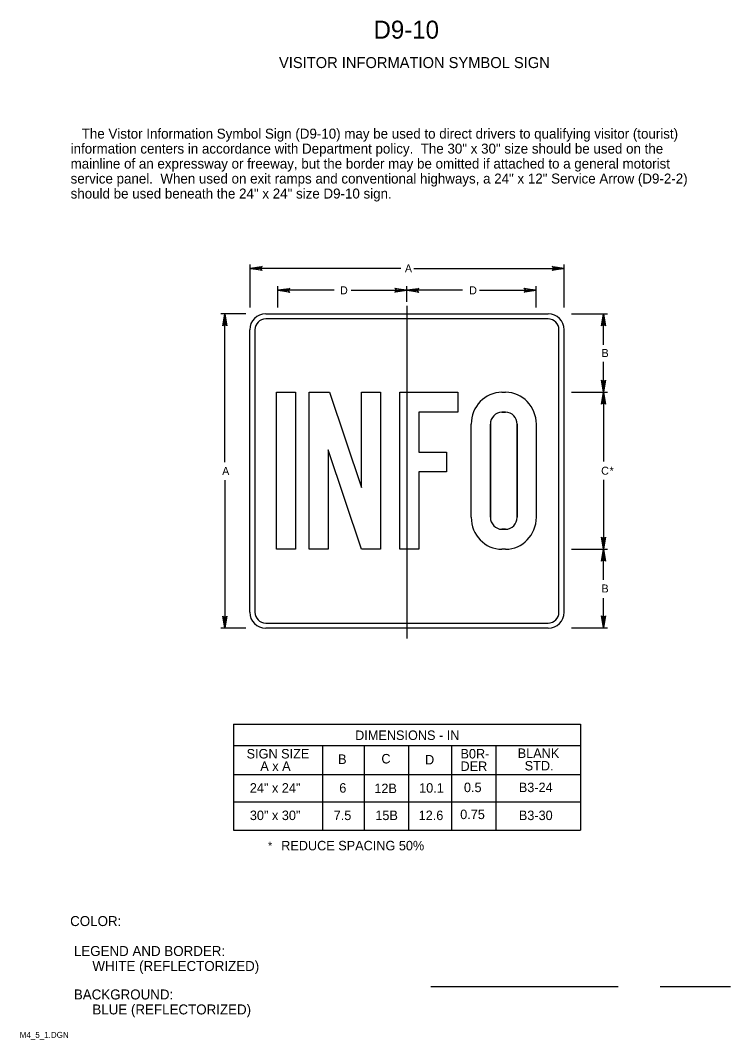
# Model space of a CAD drawing. Extents: x 0.013 to 0.191, y 0.004 to 0.259.
import ezdxf

# ---------------------------------------------------------------- set-up
doc = ezdxf.new("R2010")
doc.units = 0
doc.layers.add('1', color=7, linetype='Continuous')
doc.layers.add('3', color=7, linetype='Continuous')

# ---------------------------------------------------------------- blocks, each defined once
blk = doc.blocks.new('RARROW')
at = {"layer": '3'}
for p, q in [((-2.156, 0.285), (-2.2665, 0.384625)), ((-2.2665, 0.384625), (0, 0)), ((0, 0), (-2.2665, -0.379125)), ((-2.156, 0.285), (-2.075625, 0.12075)), ((0, 0), (-2.156, 0.285)), ((-2.14975, -0.2705), (0, 0)), ((-2.075625, 0.12075), (0, 0)), ((0, 0), (-2.074, -0.108)), ((-2.2665, -0.379125), (-2.14975, -0.2705)), ((-2.074, -0.108), (-2.14975, -0.2705))]:
    blk.add_line(p, q, dxfattribs=at)

msp = doc.modelspace()

# ---------------------------------------------------------------- linework, layer by layer
at = {"layer": '1'}
for p, q in [((0.11544, 0.01723), (0.16242, 0.01723)), ((0.17295, 0.01723), (0.19056, 0.01723))]:
    msp.add_line(p, q, dxfattribs=at)
at = {"layer": '3'}
for p, q in [((0.07023, 0.18733), (0.07023, 0.19809)), ((0.10798, 0.19709), (0.07023, 0.19709)), ((0.11123, 0.19709), (0.14886, 0.19709)), ((0.14886, 0.18733), (0.14886, 0.19809)), ((0.07713, 0.18733), (0.07713, 0.19259)), ((0.09122, 0.19159), (0.07713, 0.19159)), ((0.09549, 0.19159), (0.10948, 0.19159)), ((0.10948, 0.18872), (0.10948, 0.19259)), ((0.12343, 0.19159), (0.10948, 0.19159)), ((0.12769, 0.19159), (0.14183, 0.19159)), ((0.14183, 0.18733), (0.14183, 0.19259)), ((0.10948, 0.18772), (0.10948, 0.10443)), ((0.06915, 0.18572), (0.0629, 0.18572)), ((0.0639, 0.14859), (0.0639, 0.18572)), ((0.07411, 0.18572), (0.14486, 0.18572)), ((0.14486, 0.18442), (0.07411, 0.18442)), ((0.15073, 0.18572), (0.15973, 0.18572)), ((0.15873, 0.17794), (0.15873, 0.18572)), ((0.07011, 0.11097), (0.07011, 0.18172)), ((0.07141, 0.18172), (0.07141, 0.11097)), ((0.14886, 0.11097), (0.14886, 0.18172)), ((0.14886, 0.11097), (0.14886, 0.18172)), ((0.15873, 0.16606), (0.15873, 0.17372)), ((0.07678, 0.12675), (0.07678, 0.16606)), ((0.07678, 0.16606), (0.08159, 0.16606)), ((0.08159, 0.16606), (0.08159, 0.12675)), ((0.08496, 0.12675), (0.08496, 0.16606)), ((0.08496, 0.16606), (0.09013, 0.16606)), ((0.09013, 0.16606), (0.09807, 0.14223)), ((0.09807, 0.14223), (0.09807, 0.16606)), ((0.09807, 0.16606), (0.10289, 0.16606)), ((0.10289, 0.16606), (0.10289, 0.12675)), ((0.1077, 0.12675), (0.1077, 0.16606)), ((0.1077, 0.16606), (0.12221, 0.16606)), ((0.12221, 0.16606), (0.12221, 0.16106)), ((0.15073, 0.16606), (0.15973, 0.16606)), ((0.15873, 0.16606), (0.15873, 0.14869)), ((0.12221, 0.16106), (0.11251, 0.16106)), ((0.11251, 0.16106), (0.11251, 0.1511)), ((0.13328, 0.16106), (0.1342, 0.16106)), ((0.12558, 0.13475), (0.12558, 0.15806)), ((0.13039, 0.13475), (0.13039, 0.15806)), ((0.13709, 0.15806), (0.13709, 0.13475)), ((0.1419, 0.15806), (0.1419, 0.13475)), ((0.09807, 0.12675), (0.08978, 0.15163)), ((0.08978, 0.15163), (0.08978, 0.12675)), ((0.11251, 0.1511), (0.11937, 0.1511)), ((0.11937, 0.1511), (0.11937, 0.1461)), ((0.11937, 0.1461), (0.11251, 0.1461)), ((0.11251, 0.1461), (0.11251, 0.12675)), ((0.0639, 0.14406), (0.0639, 0.10697)), ((0.15873, 0.14412), (0.15873, 0.12675)), ((0.1342, 0.13175), (0.13328, 0.13175)), ((0.08159, 0.12675), (0.07678, 0.12675)), ((0.08978, 0.12675), (0.08496, 0.12675)), ((0.10289, 0.12675), (0.09807, 0.12675)), ((0.11251, 0.12675), (0.1077, 0.12675)), ((0.1342, 0.12675), (0.13328, 0.12675)), ((0.15073, 0.12675), (0.15973, 0.12675)), ((0.15873, 0.11912), (0.15873, 0.12675)), ((0.15873, 0.10709), (0.15873, 0.11447)), ((0.06915, 0.10697), (0.0629, 0.10697)), ((0.14486, 0.10697), (0.07411, 0.10697)), ((0.15073, 0.10709), (0.15973, 0.10709)), ((0.06602, 0.08298), (0.15294, 0.08298)), ((0.06606, 0.08298), (0.06606, 0.05641)), ((0.15294, 0.08298), (0.15294, 0.05641)), ((0.15294, 0.07754), (0.06606, 0.07754)), ((0.08831, 0.07754), (0.08831, 0.05641)), ((0.0988, 0.07754), (0.0988, 0.05641)), ((0.10992, 0.07754), (0.10992, 0.05641)), ((0.12069, 0.07754), (0.12069, 0.05641)), ((0.13175, 0.07754), (0.13175, 0.05641)), ((0.06606, 0.07031), (0.15294, 0.07031)), ((0.06606, 0.06351), (0.15294, 0.06351)), ((0.06606, 0.05641), (0.15294, 0.05641))]:
    msp.add_line(p, q, dxfattribs=at)
for points in [[(0.14486, 0.18442), (0.07411, 0.18442)], [(0.14486, 0.18442), (0.07411, 0.18442)], [(0.14486, 0.18442), (0.07411, 0.18442)], [(0.14486, 0.18442), (0.07411, 0.18442)], [(0.14486, 0.18442), (0.07411, 0.18442)], [(0.14486, 0.18442), (0.07411, 0.18442)], [(0.14486, 0.18442), (0.07411, 0.18442), (0.07411, 0.18442)], [(0.14486, 0.18442), (0.14486, 0.18442)], [(0.07141, 0.18172), (0.07141, 0.11097)], [(0.07141, 0.18172), (0.07141, 0.11097)], [(0.07141, 0.18172), (0.07141, 0.11097)], [(0.07141, 0.18172), (0.07141, 0.11097)], [(0.07141, 0.18172), (0.07141, 0.11097)], [(0.07141, 0.18172), (0.07141, 0.11097)], [(0.07141, 0.18172), (0.07141, 0.11097), (0.07141, 0.11097)], [(0.14756, 0.11097), (0.14756, 0.18172)], [(0.14756, 0.11097), (0.14756, 0.18172)], [(0.14756, 0.11097), (0.14756, 0.18172)], [(0.14756, 0.11097), (0.14756, 0.18172)], [(0.14756, 0.11097), (0.14756, 0.18172)], [(0.14756, 0.11097), (0.14756, 0.18172)], [(0.14756, 0.11097), (0.14756, 0.18172)], [(0.14756, 0.11097), (0.14756, 0.18172)], [(0.08159, 0.12675), (0.07678, 0.12675), (0.07678, 0.16606), (0.08159, 0.16606), (0.08159, 0.12675)], [(0.08978, 0.12675), (0.08496, 0.12675), (0.08496, 0.16606), (0.09013, 0.16606), (0.09807, 0.14223), (0.09807, 0.16606), (0.10289, 0.16606), (0.10289, 0.12675), (0.09807, 0.12675), (0.08978, 0.15163), (0.08978, 0.12675)], [(0.11251, 0.12675), (0.1077, 0.12675), (0.1077, 0.16606), (0.12221, 0.16606), (0.12221, 0.16106), (0.11251, 0.16106), (0.11251, 0.1511), (0.11937, 0.1511), (0.11937, 0.1461), (0.11251, 0.1461), (0.11251, 0.12675)], [(0.13328, 0.16606), (0.1342, 0.16606)], [(0.1342, 0.16106), (0.13328, 0.16106)], [(0.12558, 0.13475), (0.12558, 0.15806)], [(0.13039, 0.15806), (0.13039, 0.13475)], [(0.13709, 0.13475), (0.13709, 0.15806)], [(0.1419, 0.15806), (0.1419, 0.13475)], [(0.13328, 0.13175), (0.1342, 0.13175)], [(0.1342, 0.12675), (0.13328, 0.12675)], [(0.07411, 0.10827), (0.14486, 0.10827)], [(0.07411, 0.10827), (0.14486, 0.10827)], [(0.07411, 0.10827), (0.14486, 0.10827)], [(0.07411, 0.10827), (0.14486, 0.10827)], [(0.07411, 0.10827), (0.14486, 0.10827)], [(0.07411, 0.10827), (0.14486, 0.10827)], [(0.07411, 0.10827), (0.14486, 0.10827)], [(0.07411, 0.10827), (0.14486, 0.10827)]]:
    msp.add_lwpolyline(points, dxfattribs=at)
for centre, radius, start, end in [((0.07411, 0.18172), 0.004, 90, 180), ((0.07411, 0.18172), 0.0027, 90, 180), ((0.07411, 0.18172), 0.0027, 90, 180), ((0.07411, 0.18172), 0.0027, 90, 180), ((0.07411, 0.18172), 0.0027, 90, 180), ((0.07411, 0.18172), 0.0027, 90, 180), ((0.07411, 0.18172), 0.0027, 90, 180), ((0.07411, 0.18172), 0.0027, 90, 180), ((0.07411, 0.18172), 0.0027, 90, 180), ((0.14486, 0.18172), 0.004, 0, 90), ((0.14486, 0.18172), 0.0027, 360, 90), ((0.14486, 0.18172), 0.0027, 360, 90), ((0.14486, 0.18172), 0.0027, 360, 90), ((0.14486, 0.18172), 0.0027, 360, 90), ((0.14486, 0.18172), 0.0027, 360, 90), ((0.14486, 0.18172), 0.0027, 360, 90), ((0.14486, 0.18172), 0.0027, 360, 90), ((0.14486, 0.18172), 0.0027, 360, 90), ((0.07411, 0.11097), 0.004, 180, 270), ((0.07411, 0.11097), 0.0027, 180, 270), ((0.07411, 0.11097), 0.0027, 180, 270), ((0.07411, 0.11097), 0.0027, 180, 270), ((0.07411, 0.11097), 0.0027, 180, 270), ((0.07411, 0.11097), 0.0027, 180, 270), ((0.07411, 0.11097), 0.0027, 180, 270), ((0.07411, 0.11097), 0.0027, 180, 270), ((0.07411, 0.11097), 0.0027, 180, 270), ((0.14486, 0.11097), 0.004, 270, 0), ((0.14486, 0.11097), 0.0027, 270, 0), ((0.14486, 0.11097), 0.0027, 270, 0), ((0.14486, 0.11097), 0.0027, 270, 0), ((0.14486, 0.11097), 0.0027, 270, 0), ((0.14486, 0.11097), 0.0027, 270, 0), ((0.14486, 0.11097), 0.0027, 270, 0), ((0.14486, 0.11097), 0.0027, 270, 0), ((0.14486, 0.11097), 0.0027, 270, 0)]:
    msp.add_arc(centre, radius, start, end, dxfattribs=at)
for centre, major_axis, start_param, end_param in [((0.13328, 0.15806), (0, 0.008), 0, 1.570796), ((0.13328, 0.15806), (0, 0.008), 0, 1.570796), ((0.1342, 0.15806), (0, 0.008), 4.712389, 6.283185), ((0.1342, 0.15806), (0, 0.008), 4.712389, 6.283185), ((0.13328, 0.15806), (0, 0.003), 0, 1.570796), ((0.13328, 0.15806), (0, 0.003), 0, 1.570796), ((0.1342, 0.15806), (0, 0.003), 4.712389, 6.283185), ((0.1342, 0.15806), (0, 0.003), 4.712389, 6.283185), ((0.13328, 0.13475), (0, -0.008), 4.712389, 6.283185), ((0.13328, 0.13475), (0, -0.008), 4.712389, 6.283185), ((0.13328, 0.13475), (0, -0.003), 4.712389, 6.283185), ((0.13328, 0.13475), (0, -0.003), 4.712389, 6.283185), ((0.1342, 0.13475), (0, -0.008), 0, 1.570796), ((0.1342, 0.13475), (0, -0.003), 0, 1.570796), ((0.1342, 0.13475), (0, -0.008), 0, 1.570796), ((0.1342, 0.13475), (0, -0.003), 0, 1.570796)]:
    msp.add_ellipse(centre, major_axis=major_axis, ratio=0.962529, start_param=start_param, end_param=end_param, dxfattribs=at)

# ---------------------------------------------------------------- block references
at = {"layer": '3', "xscale": 0.0013236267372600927, "yscale": 0.001309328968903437}
for p, rotation in [((0.07023, 0.19709), 180), ((0.07713, 0.19159), 180), ((0.10948, 0.19159), 180), ((0.0639, 0.18572), 90), ((0.15873, 0.18572), 90), ((0.15873, 0.16606), -90), ((0.15873, 0.16606), 90), ((0.15873, 0.12675), -90), ((0.15873, 0.12675), 90), ((0.0639, 0.10697), -90), ((0.15873, 0.10709), -90)]:
    msp.add_blockref('RARROW', p, dxfattribs=dict(at, rotation=rotation))
for p in [(0.14886, 0.19709), (0.10948, 0.19159), (0.14183, 0.19159)]:
    msp.add_blockref('RARROW', p, dxfattribs=at)

# ---------------------------------------------------------------- texts
at = {"layer": '1'}
for s, height, p in [('D9-10', 0.0045, (0.10113, 0.25462)), ('VISITOR INFORMATION SYMBOL SIGN', 0.0027503, (0.07744, 0.24725)), ('   The Vistor Information Symbol Sign (D9-10) may be used to direct drivers to qualifying visitor (tourist)', 0.00249975, (0.02525, 0.22958)), ('information centers in accordance with Department policy.  The 30" x 30" size should be used on the', 0.0024998, (0.02525, 0.22583)), ('mainline of an expressway or freeway, but the border may be omitted if attached to a general motorist', 0.00249975, (0.02525, 0.22208)), ('service panel.  When used on exit ramps and conventional highways, a 24" x 12" Service Arrow (D9-2-2)', 0.00249975, (0.02525, 0.21833)), ('should be used beneath the 24" x 24" size D9-10 sign.', 0.0024998, (0.02525, 0.21458)), ('COLOR:', 0.0025, (0.02513, 0.03238)), (' LEGEND AND BORDER:', 0.0024998, (0.02513, 0.02488)), ('      WHITE (REFLECTORIZED)', 0.0024998, (0.02513, 0.02113)), (' BACKGROUND:', 0.0024998, (0.02513, 0.014)), ('      BLUE (REFLECTORIZED)', 0.0024998, (0.02513, 0.01025)), ('M4_5_1.DGN', 0.0015, (0.0125, 0.00438))]:
    msp.add_text(s, height=height, dxfattribs=at).set_placement(p)
at = {"layer": '3'}
for s, height, p in [('A', 0.002, (0.10898, 0.19609)), ('D', 0.002, (0.09273, 0.19059)), ('D', 0.002, (0.12508, 0.19059)), ('B', 0.002, (0.15823, 0.17489)), ('A', 0.002, (0.06321, 0.14534)), ('C', 0.002, (0.15814, 0.14541)), ('*', 0.002, (0.16025, 0.14541)), ('B', 0.002, (0.15823, 0.11592)), ('DIMENSIONS - IN', 0.0023752, (0.09652, 0.07898)), ('SIGN SIZE', 0.002375, (0.06933, 0.07435)), ('B0R-', 0.002375, (0.1229, 0.07435)), ('BLANK', 0.002375, (0.13723, 0.07448)), ('B', 0.00238, (0.09225, 0.07298)), ('C', 0.00238, (0.10309, 0.0731)), ('D', 0.00238, (0.11402, 0.07285)), ('A x A', 0.002375, (0.07276, 0.07123)), ('DER', 0.002375, (0.1229, 0.07123)), ('STD.', 0.002375, (0.13898, 0.07135)), ('24" x 24"', 0.002375, (0.07014, 0.06579)), ('6', 0.00238, (0.09254, 0.06579)), ('12B', 0.002375, (0.10132, 0.06567)), ('10.1', 0.002375, (0.11254, 0.06579)), ('0.5', 0.002375, (0.12377, 0.06592)), ('B3-24', 0.002375, (0.13751, 0.06592)), ('30" x 30"', 0.002375, (0.07014, 0.05892)), ('7.5', 0.002375, (0.09114, 0.05892)), ('15B', 0.002375, (0.10157, 0.05892)), ('12.6', 0.002375, (0.11242, 0.05892)), ('0.75', 0.002375, (0.12283, 0.05917)), ('B3-30', 0.002375, (0.13752, 0.05892)), ('REDUCE SPACING 50%', 0.0023752, (0.07799, 0.05134)), ('*', 0.002, (0.0747, 0.05152))]:
    msp.add_text(s, height=height, dxfattribs=at).set_placement(p)

doc.saveas('drawing.dxf')
